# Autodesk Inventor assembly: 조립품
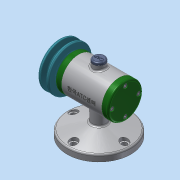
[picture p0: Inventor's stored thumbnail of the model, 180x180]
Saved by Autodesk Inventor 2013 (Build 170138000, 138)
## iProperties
Created: 2018-12
Part Number: 조립품
Document SubType Name: Assembly
Designer: dgall
Author: dgall
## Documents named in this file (15)
- C:\Users\dgall\Desktop\481207V1025\조립품.iam
- C:\Users\dgall\Desktop\481207V1025\V벨트풀리.ipt
- C:\Users\dgall\Desktop\481207V1025\고무캡.ipt
- C:\Users\dgall\Desktop\481207V1025\너트 M8.ipt
- 너트 M8.ipt
- C:\Users\dgall\Desktop\481207V1025\뒤커버.ipt
- C:\Users\dgall\Desktop\481207V1025\베어링 15 x 32 x 9.ipt
- C:\Users\dgall\Desktop\481207V1025\본체.ipt
- C:\Users\dgall\Desktop\481207V1025\볼트 M4 x 12.ipt
- C:\Users\dgall\Desktop\481207V1025\스프링와셔 8.ipt
- C:\Users\dgall\Desktop\481207V1025\앞커버.ipt
- C:\Users\dgall\Desktop\481207V1025\오일 실 15 25 7.ipt
- C:\Users\dgall\Desktop\481207V1025\와셔 8x17.ipt
- C:\Users\dgall\Desktop\481207V1025\축.ipt
- C:\Users\dgall\Desktop\481207V1025\키 3 x 3 x 12.ipt
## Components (2 placed, 2 different names)
1. V벨트풀리:1
2. 고무캡:1
